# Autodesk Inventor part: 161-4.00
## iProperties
Created: 2007-06
Part Number: 161-4.00
Document SubType Name: Modeling
Designer: btaylor
Density: 1 g/cm^3
Author: btaylor
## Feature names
1. Extrusion1
2. Extrusion2
3. Extrusion3
4. Extrusion4
5. Extrusion5
6. Fillet1
7. Fillet2
8. Fillet3
9. Fillet4
10. Extrusion6
11. Extrusion7
12. Extrusion8
13. Extrusion9
14. Extrusion11
15. Fillet5
16. Fillet6
17. Fillet7
18. Fillet8
19. Chamfer1
20. Chamfer2
21. Chamfer3
22. Fillet9
23. Fillet10
24. Fillet11
